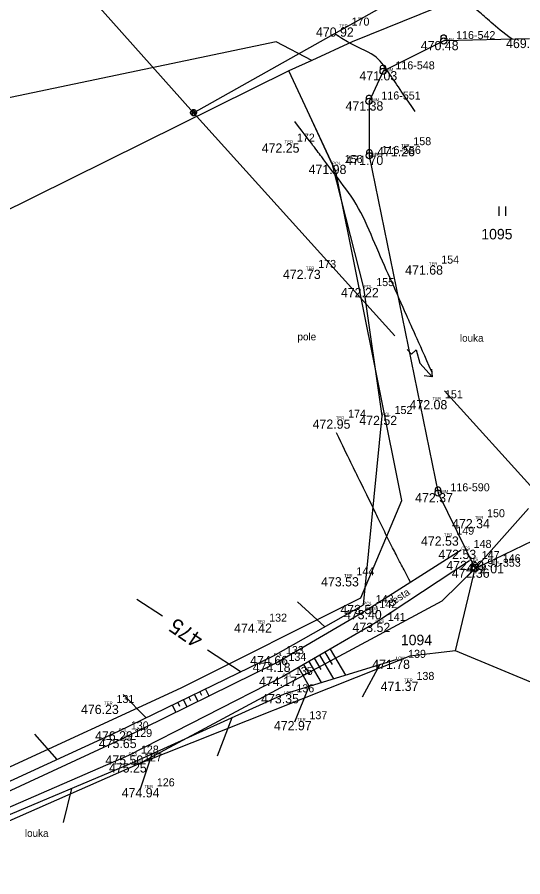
# Model space of a CAD drawing. Extents: x -604848 to -603227, y -1111879 to -1109838.
# Drawn here: x -603592.3 to -603510.2, y -1110357.3 to -1110217.6 of the extents above; entities that cross this region are included whole.
import ezdxf

# ---------------------------------------------------------------- set-up
doc = ezdxf.new("R2010")
doc.units = 0
for name, color, linetype in [('1', 7, 'Continuous'), ('10', 7, 'Continuous'), ('12', 7, 'Continuous'), ('14', 7, 'Continuous'), ('18', 7, 'Continuous'), ('19', 7, 'Continuous'), ('20', 7, 'Continuous'), ('23', 7, 'Continuous'), ('26', 7, 'Continuous'), ('28', 7, 'Continuous'), ('4', 7, 'Continuous'), ('7', 7, 'Continuous'), ('8', 7, 'Continuous'), ('9', 7, 'Continuous'), ('Default', 7, 'Continuous')]:
    doc.layers.add(name, color=color, linetype=linetype)

# ---------------------------------------------------------------- blocks, each defined once
blk = doc.blocks.new('Z601')
at = {"layer": '26'}
for p, q in [((-0.5, 0.1), (-0.4, 0.3)), ((-0.5, -0.1), (-0.5, 0.1)), ((-0.4, 0.3), (-0.3, 0.4)), ((-0.3, 0.4), (-0.1, 0.5)), ((-0.3, 0.2), (-0.3, -0.2)), ((-0.1, 0.5), (0.1, 0.5)), ((-0.1, -0.3), (-0.1, 0.3)), ((-0.1, 0.3), (0.1, 0.3)), ((0.1, 0.5), (0.3, 0.4)), ((0.1, 0.3), (0.1, -0.3)), ((0.3, 0.4), (0.4, 0.3)), ((0.3, -0.2), (0.3, 0.2)), ((0.4, 0.3), (0.5, 0.1)), ((0.5, 0.1), (0.5, -0.1)), ((-0.4, -0.3), (-0.5, -0.1)), ((-0.3, -0.4), (-0.4, -0.3)), ((-0.3, -0.2), (-0.1, -0.3)), ((-0.1, -0.5), (-0.3, -0.4)), ((0.1, -0.5), (-0.1, -0.5)), ((0.1, -0.3), (0.3, -0.2)), ((0.3, -0.4), (0.1, -0.5)), ((0.4, -0.3), (0.3, -0.4)), ((0.5, -0.1), (0.4, -0.3))]:
    blk.add_line(p, q, dxfattribs=at)
blk = doc.blocks.new('Z105')
at = {"layer": '28'}
for radius in [0.5, 0.01]:
    blk.add_circle((0, 0), radius, dxfattribs=at)
blk = doc.blocks.new('Z3060')
at = {"layer": '23'}
for p, q in [((-0.5, 0), (-0.5, 1.5)), ((0.5, 1.5), (0.5, 0))]:
    blk.add_line(p, q, dxfattribs=at)
blk = doc.blocks.new('POINT_DISPLAY')
at = {"layer": 'Default'}
blk.add_line((0, 0), (0, 0), dxfattribs=at)
blk = doc.blocks.new('Z4')
at = {"layer": '4'}
for p, q in [((-0.4, 0.7), (-0.3, 0.9)), ((-0.4, 0.3), (-0.4, 0.7)), ((-0.3, 0.9), (-0.1, 1)), ((-0.1, 1), (0.1, 1)), ((0.1, 1), (0.3, 0.9)), ((0.3, 0.9), (0.4, 0.7)), ((0.4, 0.7), (0.4, 0.3))]:
    blk.add_line(p, q, dxfattribs=at)
blk = doc.blocks.new('Z660')
at = {"layer": '12'}
for p, q in [((-3, 0), (-2, 0)), ((-2, 0), (-2, 1)), ((-2, 1), (0, 0)), ((0, 0), (3, 0)), ((2, 0.8), (3, 0)), ((3, 0), (2, -0.8))]:
    blk.add_line(p, q, dxfattribs=at)

msp = doc.modelspace()

# ---------------------------------------------------------------- linework, layer by layer
at = {"layer": '1'}
for p, q in [((-603524.13, -1110216.06), (-603537.93, -1110221.64)), ((-603550.28, -1110221.64), (-603624.32, -1110237.13)), ((-603544.5, -1110224.64), (-603550.28, -1110221.64)), ((-603537.93, -1110221.64), (-603544.5, -1110224.64)), ((-603523.07, -1110221.49), (-603532.92, -1110226.4)), ((-603509.17, -1110221.15), (-603523.07, -1110221.49)), ((-603544.5, -1110224.64), (-603548.21, -1110226.34)), ((-603548.21, -1110226.34), (-603674.17, -1110288.7)), ((-603540.61, -1110242.67), (-603548.21, -1110226.34)), ((-603532.92, -1110226.4), (-603535.2, -1110231.3)), ((-603535.2, -1110231.3), (-603535.17, -1110240.14)), ((-603535.17, -1110240.14), (-603523.99, -1110294.94)), ((-603529.87, -1110296.12), (-603540.61, -1110242.67)), ((-603517.99, -1110307.19), (-603473.51, -1110285.68)), ((-603536.51, -1110311.95), (-603529.87, -1110296.12)), ((-603523.99, -1110294.94), (-603517.99, -1110307.19)), ((-603517.99, -1110307.19), (-603509.32, -1110297.44)), ((-603523.35, -1110312.43), (-603517.99, -1110307.19)), ((-603521.14, -1110320.58), (-603517.99, -1110307.19)), ((-603572.67, -1110338.96), (-603523.35, -1110312.43)), ((-603565.71, -1110326.59), (-603536.51, -1110311.95)), ((-603521.14, -1110320.58), (-603528.6, -1110321.42)), ((-603499.33, -1110329.65), (-603521.14, -1110320.58)), ((-603528.6, -1110321.42), (-603572.67, -1110338.96)), ((-603621.37, -1110352.15), (-603565.71, -1110326.59)), ((-603572.67, -1110338.96), (-603614.3, -1110357.26))]:
    msp.add_line(p, q, dxfattribs=at)
at = {"layer": '10'}
for p, q in [((-603541.16, -1110241.61), (-603545.18, -1110232.86)), ((-603536.04, -1110261.61), (-603541.16, -1110241.61)), ((-603533.06, -1110282.38), (-603536.04, -1110261.61)), ((-603536.11, -1110313.09), (-603533.06, -1110282.38)), ((-603550.69, -1110321.38), (-603536.11, -1110313.09)), ((-603575.88, -1110333.62), (-603550.69, -1110321.38)), ((-603530.86, -1110321.99), (-603549, -1110327.59)), ((-603549, -1110327.59), (-603573.72, -1110338.82)), ((-603602.56, -1110345.83), (-603575.88, -1110333.62)), ((-603573.72, -1110338.82), (-603600.67, -1110350.19))]:
    msp.add_line(p, q, dxfattribs=at)
at = {"layer": '12'}
for p, q in [((-603563.7, -1110233.14), (-603524.77, -1110211.25)), ((-603580.25, -1110214.53), (-603563.7, -1110233.14)), ((-603563.7, -1110233.14), (-603531, -1110269.39)), ((-603522.96, -1110278.3), (-603507.98, -1110294.9))]:
    msp.add_line(p, q, dxfattribs=at)
at = {"layer": '4'}
for p, q in [((-603535.54, -1110313.92), (-603520.22, -1110304.14)), ((-603518.9, -1110305.94), (-603534.16, -1110316)), ((-603550.29, -1110322.48), (-603535.54, -1110313.92)), ((-603534.16, -1110316), (-603549.25, -1110324.77)), ((-603575.32, -1110334.85), (-603550.29, -1110322.48)), ((-603549.25, -1110324.77), (-603574.24, -1110337.54)), ((-603602.08, -1110347.24), (-603575.32, -1110334.85)), ((-603574.24, -1110337.54), (-603601.02, -1110349.16))]:
    msp.add_line(p, q, dxfattribs=at)
at = {"layer": '7'}
for p, q in [((-603568.74, -1110314.91), (-603572.88, -1110312.21)), ((-603546.81, -1110312.6), (-603542.37, -1110316.65)), ((-603561.43, -1110320.38), (-603555.99, -1110323.96)), ((-603533.43, -1110322.79), (-603536.33, -1110328.09)), ((-603544.98, -1110326.35), (-603547.28, -1110332.14)), ((-603575.13, -1110327.67), (-603571.4, -1110331.44)), ((-603557.46, -1110331.44), (-603559.85, -1110337.67)), ((-603589.5, -1110334.08), (-603585.89, -1110338.2)), ((-603570.46, -1110337.34), (-603572.42, -1110343.18)), ((-603583.49, -1110342.94), (-603584.85, -1110348.45))]:
    msp.add_line(p, q, dxfattribs=at)
for points in [[(-603511.97, -1110221.22), (-603514.93, -1110219.06), (-603517.5, -1110216.23), (-603520.84, -1110214.73), (-603522.72, -1110213.89), (-603524.6, -1110213.05), (-603526.47, -1110212.21)], [(-603527.69, -1110232.96), (-603529.25, -1110230.68), (-603530.81, -1110228.41), (-603532.37, -1110226.13), (-603534.26, -1110223.38), (-603537.84, -1110222.34), (-603540.58, -1110220.44)], [(-603525.01, -1110275.25), (-603527.25, -1110270.2), (-603529.5, -1110265.16), (-603531.74, -1110260.12), (-603534.28, -1110254.43), (-603536.66, -1110248.53), (-603540.43, -1110243.56), (-603542.7, -1110240.57), (-603544.97, -1110237.59), (-603547.24, -1110234.6)], [(-603528.48, -1110309.41), (-603529.23, -1110307.98), (-603529.97, -1110306.54), (-603530.72, -1110305.11), (-603532.05, -1110302.54), (-603533.27, -1110299.92), (-603534.54, -1110297.32), (-603536.52, -1110293.27), (-603538.51, -1110289.22), (-603540.49, -1110285.17)]]:
    msp.add_open_spline(points, degree=3, dxfattribs=at)
at = {"layer": '8'}
for p, q in [((-603543.23, -1110321.27), (-603540.99, -1110325.12)), ((-603542.36, -1110320.77), (-603541.18, -1110322.79)), ((-603541.5, -1110320.26), (-603539.03, -1110324.51)), ((-603544.96, -1110322.27), (-603542.95, -1110325.72)), ((-603544.09, -1110321.77), (-603543.03, -1110323.6)), ((-603546.68, -1110323.28), (-603544.91, -1110326.33)), ((-603545.82, -1110322.78), (-603544.88, -1110324.4)), ((-603561.76, -1110326.76), (-603561.21, -1110327.88)), ((-603564.45, -1110328.07), (-603564.18, -1110328.64)), ((-603563.55, -1110327.63), (-603563, -1110328.76)), ((-603562.66, -1110327.19), (-603562.38, -1110327.76)), ((-603567.15, -1110329.38), (-603566.59, -1110330.54)), ((-603566.25, -1110328.94), (-603565.97, -1110329.52)), ((-603565.35, -1110328.5), (-603564.8, -1110329.65))]:
    msp.add_line(p, q, dxfattribs=at)

# ---------------------------------------------------------------- block references
at = {"layer": '12', "xscale": 0.9999969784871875, "yscale": 0.9999969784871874, "rotation": -47.94325825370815}
msp.add_blockref('Z660', (-603526.98, -1110273.84), dxfattribs=at)
at = {"layer": '18'}
for p in [(-603540.04, -1110219.3), (-603523.07, -1110221.49), (-603532.92, -1110226.4), (-603535.2, -1110231.3), (-603548.91, -1110238.14), (-603530.01, -1110238.72), (-603535.17, -1110240.14), (-603541.16, -1110241.61), (-603525.48, -1110257.95), (-603545.45, -1110258.66), (-603536.04, -1110261.61), (-603524.88, -1110279.83), (-603540.6, -1110282.98), (-603533.06, -1110282.38), (-603523.99, -1110294.94), (-603518.04, -1110299.15), (-603523.04, -1110301.98), (-603520.22, -1110304.14), (-603518.9, -1110305.94), (-603517.99, -1110307.19), (-603515.5, -1110306.47), (-603539.26, -1110308.59), (-603536.11, -1110313.09), (-603535.54, -1110313.92), (-603553.42, -1110316.12), (-603534.16, -1110316), (-603550.69, -1110321.38), (-603550.29, -1110322.48), (-603530.86, -1110321.99), (-603549.25, -1110324.77), (-603529.5, -1110325.58), (-603549, -1110327.59), (-603578.21, -1110329.32), (-603546.88, -1110331.96), (-603575.88, -1110333.62), (-603575.32, -1110334.85), (-603574.24, -1110337.54), (-603573.72, -1110338.82), (-603571.66, -1110342.86)]:
    msp.add_blockref('POINT_DISPLAY', p, dxfattribs=at)
at = {"layer": '23'}
msp.add_blockref('Z3060', (-603513.56, -1110249.88), dxfattribs=at)
at = {"layer": '26'}
msp.add_blockref('Z601', (-603563.7, -1110233.14), dxfattribs=at)
at = {"layer": '28'}
for p in [(-603523.07, -1110221.49), (-603532.92, -1110226.4), (-603535.2, -1110231.3), (-603535.17, -1110240.14), (-603523.99, -1110294.94), (-603517.99, -1110307.19)]:
    msp.add_blockref('Z105', p, dxfattribs=at)
at = {"layer": '4'}
for p in [(-603523.07, -1110221.49), (-603532.92, -1110226.4), (-603535.2, -1110231.3), (-603535.17, -1110240.14), (-603523.99, -1110294.94), (-603517.99, -1110307.19)]:
    msp.add_blockref('Z4', p, dxfattribs=at)

# ---------------------------------------------------------------- texts
at = {"layer": '14'}
for s, p in [('1095', (-603516.97, -1110253.72)), ('1094', (-603530.03, -1110319.64))]:
    msp.add_text(s, height=1.7, dxfattribs=at).set_placement(p)
at = {"layer": '18'}
for s, p in [('TER', (-603540.04, -1110219.3)), ('UMM', (-603523.07, -1110221.49)), ('UMM', (-603532.92, -1110226.4)), ('UMM', (-603535.2, -1110231.3)), ('TER', (-603548.91, -1110238.14)), ('TER', (-603530.01, -1110238.72)), ('UMM', (-603535.17, -1110240.14)), ('POL', (-603541.16, -1110241.61)), ('TER', (-603545.45, -1110258.66)), ('TER', (-603525.48, -1110257.95)), ('POL', (-603536.04, -1110261.61)), ('TER', (-603524.88, -1110279.83)), ('POL', (-603533.06, -1110282.38)), ('TER', (-603540.6, -1110282.98)), ('UMM', (-603523.99, -1110294.94)), ('TER', (-603518.04, -1110299.15)), ('TER', (-603523.04, -1110301.98)), ('CES', (-603520.22, -1110304.14)), ('CES', (-603518.9, -1110305.94)), ('UMM', (-603517.99, -1110307.19)), ('TER', (-603515.5, -1110306.47)), ('TER', (-603539.26, -1110308.59)), ('POL', (-603536.11, -1110313.09)), ('CES', (-603535.54, -1110313.92)), ('TER', (-603553.42, -1110316.12)), ('CES', (-603534.16, -1110316)), ('POL', (-603550.69, -1110321.38)), ('CES', (-603550.29, -1110322.48)), ('LOU', (-603530.86, -1110321.99)), ('CES', (-603549.25, -1110324.77)), ('TER', (-603529.5, -1110325.58)), ('LOU', (-603549, -1110327.59)), ('TER', (-603578.21, -1110329.32)), ('TER', (-603546.88, -1110331.96)), ('POL', (-603575.88, -1110333.62)), ('CES', (-603575.32, -1110334.85)), ('CES', (-603574.24, -1110337.54)), ('LOU', (-603573.72, -1110338.82)), ('TER', (-603571.66, -1110342.86))]:
    msp.add_text(s, height=0.5, dxfattribs=at).set_placement(p)
at = {"layer": '19'}
for s, p in [('170', (-603538.04, -1110219)), ('116-542', (-603521.07, -1110221.19)), ('116-548', (-603530.92, -1110226.1)), ('116-551', (-603533.2, -1110231)), ('172', (-603546.91, -1110237.84)), ('158', (-603528.01, -1110238.42)), ('116-556', (-603533.17, -1110239.84)), ('156', (-603539.16, -1110241.31)), ('173', (-603543.45, -1110258.36)), ('154', (-603523.48, -1110257.65)), ('155', (-603534.04, -1110261.31)), ('151', (-603522.88, -1110279.53)), ('152', (-603531.06, -1110282.08)), ('174', (-603538.6, -1110282.68)), ('116-590', (-603521.99, -1110294.64)), ('150', (-603516.04, -1110298.85)), ('149', (-603521.04, -1110301.68)), ('148', (-603518.22, -1110303.84)), ('147', (-603516.9, -1110305.64)), ('91-353', (-603515.99, -1110306.89)), ('146', (-603513.5, -1110306.17)), ('144', (-603537.26, -1110308.29)), ('143', (-603534.11, -1110312.79)), ('142', (-603533.54, -1110313.62)), ('132', (-603551.42, -1110315.82)), ('141', (-603532.16, -1110315.7)), ('133', (-603548.69, -1110321.08)), ('134', (-603548.29, -1110322.18)), ('139', (-603528.86, -1110321.69)), ('135', (-603547.25, -1110324.47)), ('138', (-603527.5, -1110325.28)), ('136', (-603547, -1110327.29)), ('131', (-603576.21, -1110329.02)), ('137', (-603544.88, -1110331.66)), ('130', (-603573.88, -1110333.32)), ('129', (-603573.32, -1110334.55)), ('128', (-603572.24, -1110337.24)), ('127', (-603571.72, -1110338.52)), ('126', (-603569.66, -1110342.56))]:
    msp.add_text(s, height=1.3, dxfattribs=at).set_placement(p)
at = {"layer": '20'}
for s, p in [('470.92 ', (-603543.82, -1110220.8)), ('470.48 ', (-603526.8, -1110222.99)), ('469.88 ', (-603512.95, -1110222.65)), ('471.03 ', (-603536.76, -1110227.9)), ('471.38 ', (-603539.02, -1110232.8)), ('472.25 ', (-603552.63, -1110239.64)), ('471.26 ', (-603533.89, -1110240.22)), ('471.70 ', (-603539.03, -1110241.64)), ('471.98 ', (-603545.01, -1110243.11)), ('471.68 ', (-603529.33, -1110259.45)), ('472.73 ', (-603549.19, -1110260.16)), ('472.22 ', (-603539.76, -1110263.11)), ('472.08 ', (-603528.63, -1110281.33)), ('472.95 ', (-603544.36, -1110284.48)), ('472.52 ', (-603536.78, -1110283.88)), ('472.37 ', (-603527.72, -1110296.44)), ('472.34 ', (-603521.72, -1110300.65)), ('472.53 ', (-603526.77, -1110303.48)), ('472.53 ', (-603523.94, -1110305.64)), ('472.63 ', (-603522.66, -1110307.44)), ('472.36 ', (-603521.77, -1110308.69)), ('472.01 ', (-603519.43, -1110307.97)), ('473.53 ', (-603542.99, -1110310.09)), ('473.50 ', (-603539.86, -1110314.59)), ('473.40 ', (-603539.28, -1110315.42)), ('474.42 ', (-603557.11, -1110317.62)), ('473.52 ', (-603537.89, -1110317.5)), ('474.66 ', (-603554.5, -1110322.88)), ('474.18 ', (-603554.09, -1110323.98)), ('471.78 ', (-603534.69, -1110323.49)), ('474.17 ', (-603553.06, -1110326.27)), ('471.37 ', (-603533.32, -1110327.08)), ('473.35 ', (-603552.72, -1110329.09)), ('476.23 ', (-603581.97, -1110330.82)), ('472.97 ', (-603550.65, -1110333.46)), ('476.29 ', (-603579.69, -1110335.12)), ('475.65 ', (-603579.08, -1110336.35)), ('475.50 ', (-603578, -1110339.04)), ('475.25 ', (-603577.44, -1110340.32)), ('474.94 ', (-603575.36, -1110344.36))]:
    msp.add_text(s, height=1.5, dxfattribs=at).set_placement(p)
at = {"layer": '7'}
msp.add_text('475', height=2.5, rotation=145.8, dxfattribs=at).set_placement((-603561.93, -1110318.22))
at = {"layer": '9'}
for s, p in [('pole', (-603546.82, -1110270.12)), ('louka', (-603520.45, -1110270.34)), ('louka', (-603591.08, -1110350.77))]:
    msp.add_text(s, height=1.2, dxfattribs=at).set_placement(p)
msp.add_text('cesta', height=1.2, rotation=33.3, dxfattribs=at).set_placement((-603531.65, -1110313.43))

doc.saveas('drawing.dxf')
